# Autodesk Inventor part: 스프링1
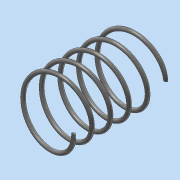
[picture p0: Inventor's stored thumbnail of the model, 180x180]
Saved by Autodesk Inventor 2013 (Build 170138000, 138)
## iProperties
Created: 2015-11
Part Number: 스프링1
Material: 강철, 탄소
Document SubType Name: Modeling
Designer: dgall
Density: 7.87 g/cm^3
Mass: 1.54359 g
Surface Area: 7.88921 cm^2
Volume: 0.196136 cm^3
Author: dgall
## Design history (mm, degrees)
sketch "스케치1"
  geometry: L1 (0, 0)-(8, 0); L2 (0, 0)-(0, 16.67); L3 (0, 16.67)-(8, 16.67); C1 r 0.5 at (8, 0)
  constraints: 6 end point, 2 perpendicular, 1 centre point, 1 coincident, 1 horizontal, 1 vertical alignment
  dimensions: "d0" = 16 diameter of L1.end L2; "d2" = 16.66987 distance of L1.start L2.end (derived); "d3" = 1 diameter of C1
feature "코일1" sketch "스케치1" pitch "d4" = 10; turns "d6" = 5; dims "d5" = 16.66987 (= d2), "d7" = 0, angle "d8" = 90 deg, angle "d9" = 90 deg, "d10" = 0, "d11" = 0
node "작업 평면1"
feature "분할1"
feature "분할2"
node "솔리드1"
other parameters: "d12" = 25
